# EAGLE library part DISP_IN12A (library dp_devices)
IN-12A Nixie Display
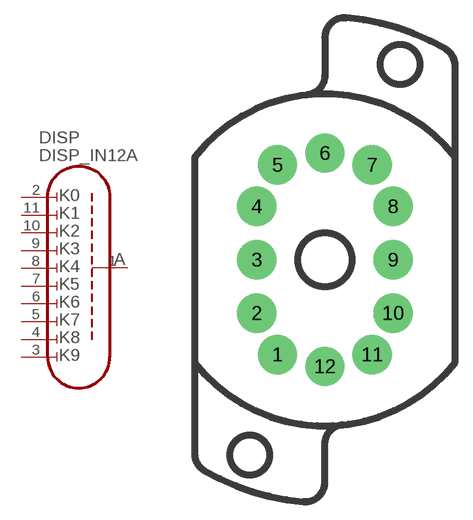
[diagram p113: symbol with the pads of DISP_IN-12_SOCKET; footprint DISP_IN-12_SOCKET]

Designator prefix DISP

## DISP_IN12A  [DISP_IN-12_SOCKET]
1  ANODE  in
2  K0  in
3  K9  in
4  K8  in
5  K7  in
6  K6  in
7  K5  in
8  K4  in
9  K3  in
10  K2  in
11  K1  in

## Footprint DISP_IN-12_SOCKET (pad centres in mm)
drill 2.3 round: 1 -4,-8; 2 -5.75,-4.5; 3 -5.75,0; 4 -5.75,4.5; 5 -4,8; 6 0,9; 7 4,8; 8 5.75,4.5; 9 5.75,0; 10 5.75,-4.5; 11 4,-8; 12 0,-9
hole 3.3 at 6.35,16.5
hole 3.3 at -6.35,-16.5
